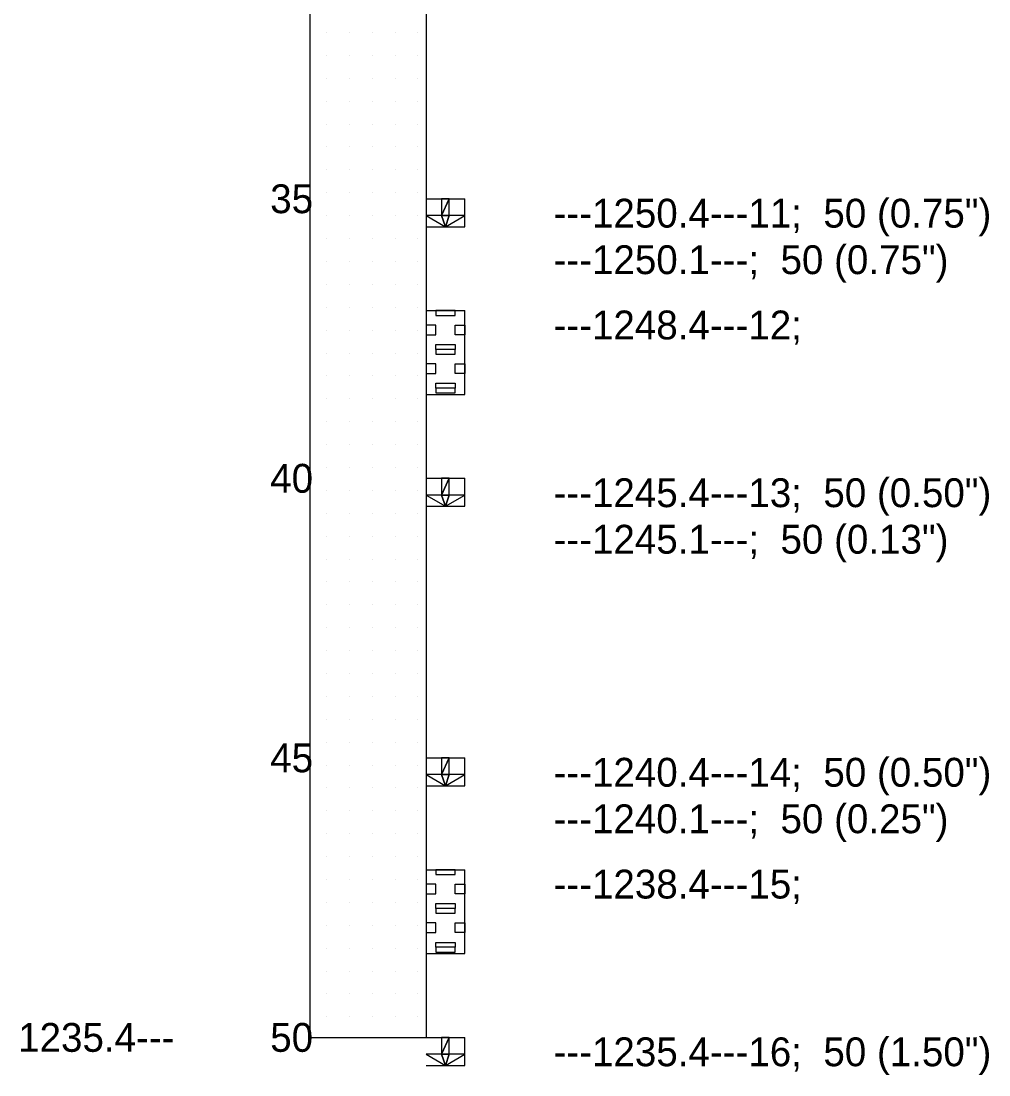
# Model space of a CAD drawing. Extents: x 2150148.6 to 2150220.1, y 143803.7 to 143875.1.
# Drawn here: x 2150175.114 to 2150179.278, y 143815.708 to 143820.239 of the extents above; entities that cross this region are included whole.
import ezdxf

# ---------------------------------------------------------------- set-up
doc = ezdxf.new("R2010")
doc.units = 0
doc.layers.add('Default', color=7, linetype='Continuous')

# ---------------------------------------------------------------- blocks, each defined once
blk = doc.blocks.new('POINT_DISPLAY')
at = {"layer": 'Default'}
blk.add_line((0, 0), (0, 0), dxfattribs=at)

msp = doc.modelspace()

# ---------------------------------------------------------------- linework, layer by layer
at = {"layer": 'Default'}
for points in [[(2150176.3564, 143827.8881), (2150176.3564, 143815.8689)], [(2150176.8564, 143827.8881), (2150176.8564, 143815.8689)], [(2150176.8564, 143819.4746), (2150177.023, 143819.4746)], [(2150177.023, 143819.3544), (2150177.023, 143819.4746)], [(2150176.8564, 143819.3544), (2150177.023, 143819.3544)], [(2150176.8564, 143818.9939), (2150177.023, 143818.9939)], [(2150177.023, 143818.6333), (2150177.023, 143818.9939)], [(2150176.8564, 143818.6333), (2150177.023, 143818.6333)], [(2150176.8564, 143818.2727), (2150177.023, 143818.2727)], [(2150177.023, 143818.1525), (2150177.023, 143818.2727)], [(2150176.8564, 143818.1525), (2150177.023, 143818.1525)], [(2150176.8564, 143817.0708), (2150177.023, 143817.0708)], [(2150177.023, 143816.9506), (2150177.023, 143817.0708)], [(2150176.8564, 143816.9506), (2150177.023, 143816.9506)], [(2150176.8564, 143816.59), (2150177.023, 143816.59)], [(2150177.023, 143816.2294), (2150177.023, 143816.59)], [(2150176.8564, 143816.2294), (2150177.023, 143816.2294)], [(2150176.3564, 143815.8689), (2150176.8564, 143815.8689)], [(2150176.8564, 143815.8689), (2150177.023, 143815.8689)], [(2150177.023, 143815.7487), (2150177.023, 143815.8689)], [(2150176.8564, 143815.7487), (2150177.023, 143815.7487)]]:
    msp.add_lwpolyline(points, dxfattribs=at)
for points in [[(2150176.923, 143819.4025), (2150176.9564, 143819.4025), (2150176.9564, 143819.4746), (2150176.923, 143819.4025)], [(2150176.923, 143819.4025), (2150176.9564, 143819.4746), (2150176.923, 143819.4746), (2150176.923, 143819.4025)], [(2150176.923, 143819.4025), (2150176.8564, 143819.4025), (2150176.9397, 143819.3544), (2150176.923, 143819.4025)], [(2150176.923, 143819.4025), (2150176.9397, 143819.3544), (2150176.9564, 143819.4025), (2150176.923, 143819.4025)], [(2150176.9397, 143819.3544), (2150177.023, 143819.4025), (2150176.9564, 143819.4025), (2150176.9397, 143819.3544)], [(2150176.898, 143818.9939), (2150176.898, 143818.973), (2150176.9814, 143818.973), (2150176.9814, 143818.9939)], [(2150176.8564, 143818.8897), (2150176.898, 143818.8897), (2150176.898, 143818.9314), (2150176.8564, 143818.9314)], [(2150177.023, 143818.8897), (2150176.9814, 143818.8897), (2150176.9814, 143818.9314), (2150177.023, 143818.9314)], [(2150176.898, 143818.8272), (2150176.898, 143818.848), (2150176.9814, 143818.848), (2150176.9814, 143818.8272)], [(2150176.898, 143818.8272), (2150176.898, 143818.8064), (2150176.9814, 143818.8064), (2150176.9814, 143818.8272)], [(2150176.8564, 143818.723), (2150176.898, 143818.723), (2150176.898, 143818.7647), (2150176.8564, 143818.7647)], [(2150177.023, 143818.723), (2150176.9814, 143818.723), (2150176.9814, 143818.7647), (2150177.023, 143818.7647)], [(2150176.898, 143818.6605), (2150176.898, 143818.6814), (2150176.9814, 143818.6814), (2150176.9814, 143818.6605)], [(2150176.898, 143818.6605), (2150176.898, 143818.6397), (2150176.9814, 143818.6397), (2150176.9814, 143818.6605)], [(2150176.923, 143818.2006), (2150176.9564, 143818.2006), (2150176.9564, 143818.2727), (2150176.923, 143818.2006)], [(2150176.923, 143818.2006), (2150176.9564, 143818.2727), (2150176.923, 143818.2727), (2150176.923, 143818.2006)], [(2150176.923, 143818.2006), (2150176.8564, 143818.2006), (2150176.9397, 143818.1525), (2150176.923, 143818.2006)], [(2150176.923, 143818.2006), (2150176.9397, 143818.1525), (2150176.9564, 143818.2006), (2150176.923, 143818.2006)], [(2150176.9397, 143818.1525), (2150177.023, 143818.2006), (2150176.9564, 143818.2006), (2150176.9397, 143818.1525)], [(2150176.923, 143816.9987), (2150176.9564, 143816.9987), (2150176.9564, 143817.0708), (2150176.923, 143816.9987)], [(2150176.923, 143816.9987), (2150176.9564, 143817.0708), (2150176.923, 143817.0708), (2150176.923, 143816.9987)], [(2150176.923, 143816.9987), (2150176.8564, 143816.9987), (2150176.9397, 143816.9506), (2150176.923, 143816.9987)], [(2150176.923, 143816.9987), (2150176.9397, 143816.9506), (2150176.9564, 143816.9987), (2150176.923, 143816.9987)], [(2150176.9397, 143816.9506), (2150177.023, 143816.9987), (2150176.9564, 143816.9987), (2150176.9397, 143816.9506)], [(2150176.898, 143816.59), (2150176.898, 143816.5692), (2150176.9814, 143816.5692), (2150176.9814, 143816.59)], [(2150176.8564, 143816.4858), (2150176.898, 143816.4858), (2150176.898, 143816.5275), (2150176.8564, 143816.5275)], [(2150177.023, 143816.4858), (2150176.9814, 143816.4858), (2150176.9814, 143816.5275), (2150177.023, 143816.5275)], [(2150176.898, 143816.4233), (2150176.898, 143816.4442), (2150176.9814, 143816.4442), (2150176.9814, 143816.4233)], [(2150176.898, 143816.4233), (2150176.898, 143816.4025), (2150176.9814, 143816.4025), (2150176.9814, 143816.4233)], [(2150176.8564, 143816.3192), (2150176.898, 143816.3192), (2150176.898, 143816.3609), (2150176.8564, 143816.3609)], [(2150177.023, 143816.3192), (2150176.9814, 143816.3192), (2150176.9814, 143816.3609), (2150177.023, 143816.3609)], [(2150176.898, 143816.2567), (2150176.898, 143816.2775), (2150176.9814, 143816.2775), (2150176.9814, 143816.2567)], [(2150176.898, 143816.2567), (2150176.898, 143816.2359), (2150176.9814, 143816.2359), (2150176.9814, 143816.2567)], [(2150176.923, 143815.7967), (2150176.9564, 143815.7967), (2150176.9564, 143815.8689), (2150176.923, 143815.7967)], [(2150176.923, 143815.7967), (2150176.9564, 143815.8689), (2150176.923, 143815.8689), (2150176.923, 143815.7967)], [(2150176.923, 143815.7967), (2150176.8564, 143815.7967), (2150176.9397, 143815.7487), (2150176.923, 143815.7967)], [(2150176.923, 143815.7967), (2150176.9397, 143815.7487), (2150176.9564, 143815.7967), (2150176.923, 143815.7967)], [(2150176.9397, 143815.7487), (2150177.023, 143815.7967), (2150176.9564, 143815.7967), (2150176.9397, 143815.7487)]]:
    msp.add_lwpolyline(points, close=True, dxfattribs=at)

# ---------------------------------------------------------------- block references
at = {"layer": 'Default', "xscale": 0.39369999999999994, "yscale": 0.3936999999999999}
for p in [(2150176.4275, 143820.1893), (2150176.5259, 143820.1893), (2150176.6244, 143820.1893), (2150176.7228, 143820.1893), (2150176.8212, 143820.1893), (2150176.4275, 143820.0909), (2150176.5259, 143820.0909), (2150176.6244, 143820.0909), (2150176.7228, 143820.0909), (2150176.8212, 143820.0909), (2150176.4275, 143819.9925), (2150176.5259, 143819.9925), (2150176.6244, 143819.9925), (2150176.7228, 143819.9925), (2150176.8212, 143819.9925), (2150176.4275, 143819.8941), (2150176.5259, 143819.8941), (2150176.6244, 143819.8941), (2150176.7228, 143819.8941), (2150176.8212, 143819.8941), (2150176.4275, 143819.7956), (2150176.5259, 143819.7956), (2150176.6244, 143819.7956), (2150176.7228, 143819.7956), (2150176.8212, 143819.7956), (2150176.4275, 143819.6972), (2150176.5259, 143819.6972), (2150176.6244, 143819.6972), (2150176.7228, 143819.6972), (2150176.8212, 143819.6972), (2150176.4275, 143819.5988), (2150176.5259, 143819.5988), (2150176.6244, 143819.5988), (2150176.7228, 143819.5988), (2150176.8212, 143819.5988), (2150176.4275, 143819.5004), (2150176.5259, 143819.5004), (2150176.6244, 143819.5004), (2150176.7228, 143819.5004), (2150176.8212, 143819.5004), (2150176.4275, 143819.4019), (2150176.5259, 143819.4019), (2150176.6244, 143819.4019), (2150176.7228, 143819.4019), (2150176.8212, 143819.4019), (2150176.4275, 143819.3035), (2150176.5259, 143819.3035), (2150176.6244, 143819.3035), (2150176.7228, 143819.3035), (2150176.8212, 143819.3035), (2150176.4275, 143819.2051), (2150176.5259, 143819.2051), (2150176.6244, 143819.2051), (2150176.7228, 143819.2051), (2150176.8212, 143819.2051), (2150176.4275, 143819.1067), (2150176.5259, 143819.1067), (2150176.6244, 143819.1067), (2150176.7228, 143819.1067), (2150176.8212, 143819.1067), (2150176.4275, 143819.0082), (2150176.5259, 143819.0082), (2150176.6244, 143819.0082), (2150176.7228, 143819.0082), (2150176.8212, 143819.0082), (2150176.4275, 143818.9098), (2150176.5259, 143818.9098), (2150176.6244, 143818.9098), (2150176.7228, 143818.9098), (2150176.8212, 143818.9098), (2150176.4275, 143818.8114), (2150176.5259, 143818.8114), (2150176.6244, 143818.8114), (2150176.7228, 143818.8114), (2150176.8212, 143818.8114), (2150176.4275, 143818.713), (2150176.5259, 143818.713), (2150176.6244, 143818.713), (2150176.7228, 143818.713), (2150176.8212, 143818.713), (2150176.4275, 143818.6145), (2150176.5259, 143818.6145), (2150176.6244, 143818.6145), (2150176.7228, 143818.6145), (2150176.8212, 143818.6145), (2150176.4275, 143818.5161), (2150176.5259, 143818.5161), (2150176.6244, 143818.5161), (2150176.7228, 143818.5161), (2150176.8212, 143818.5161), (2150176.4275, 143818.4177), (2150176.5259, 143818.4177), (2150176.6244, 143818.4177), (2150176.7228, 143818.4177), (2150176.8212, 143818.4177), (2150176.4275, 143818.3193), (2150176.5259, 143818.3193), (2150176.6244, 143818.3193), (2150176.7228, 143818.3193), (2150176.8212, 143818.3193), (2150176.4275, 143818.2208), (2150176.5259, 143818.2208), (2150176.6244, 143818.2208), (2150176.7228, 143818.2208), (2150176.8212, 143818.2208), (2150176.4275, 143818.1224), (2150176.5259, 143818.1224), (2150176.6244, 143818.1224), (2150176.7228, 143818.1224), (2150176.8212, 143818.1224), (2150176.4275, 143818.024), (2150176.5259, 143818.024), (2150176.6244, 143818.024), (2150176.7228, 143818.024), (2150176.8212, 143818.024), (2150176.4275, 143817.9256), (2150176.5259, 143817.9256), (2150176.6244, 143817.9256), (2150176.7228, 143817.9256), (2150176.8212, 143817.9256), (2150176.4275, 143817.8271), (2150176.5259, 143817.8271), (2150176.6244, 143817.8271), (2150176.7228, 143817.8271), (2150176.8212, 143817.8271), (2150176.4275, 143817.7287), (2150176.5259, 143817.7287), (2150176.6244, 143817.7287), (2150176.7228, 143817.7287), (2150176.8212, 143817.7287), (2150176.4275, 143817.6303), (2150176.5259, 143817.6303), (2150176.6244, 143817.6303), (2150176.7228, 143817.6303), (2150176.8212, 143817.6303), (2150176.4275, 143817.5319), (2150176.5259, 143817.5319), (2150176.6244, 143817.5319), (2150176.7228, 143817.5319), (2150176.8212, 143817.5319), (2150176.4275, 143817.4334), (2150176.5259, 143817.4334), (2150176.6244, 143817.4334), (2150176.7228, 143817.4334), (2150176.8212, 143817.4334), (2150176.4275, 143817.335), (2150176.5259, 143817.335), (2150176.6244, 143817.335), (2150176.7228, 143817.335), (2150176.8212, 143817.335), (2150176.4275, 143817.2366), (2150176.5259, 143817.2366), (2150176.6244, 143817.2366), (2150176.7228, 143817.2366), (2150176.8212, 143817.2366), (2150176.4275, 143817.1382), (2150176.5259, 143817.1382), (2150176.6244, 143817.1382), (2150176.7228, 143817.1382), (2150176.8212, 143817.1382), (2150176.4275, 143817.0397), (2150176.5259, 143817.0397), (2150176.6244, 143817.0397), (2150176.7228, 143817.0397), (2150176.8212, 143817.0397), (2150176.4275, 143816.9413), (2150176.5259, 143816.9413), (2150176.6244, 143816.9413), (2150176.7228, 143816.9413), (2150176.8212, 143816.9413), (2150176.4275, 143816.8429), (2150176.5259, 143816.8429), (2150176.6244, 143816.8429), (2150176.7228, 143816.8429), (2150176.8212, 143816.8429), (2150176.4275, 143816.7445), (2150176.5259, 143816.7445), (2150176.6244, 143816.7445), (2150176.7228, 143816.7445), (2150176.8212, 143816.7445), (2150176.4275, 143816.646), (2150176.5259, 143816.646), (2150176.6244, 143816.646), (2150176.7228, 143816.646), (2150176.8212, 143816.646), (2150176.4275, 143816.5476), (2150176.5259, 143816.5476), (2150176.6244, 143816.5476), (2150176.7228, 143816.5476), (2150176.8212, 143816.5476), (2150176.4275, 143816.4492), (2150176.5259, 143816.4492), (2150176.6244, 143816.4492), (2150176.7228, 143816.4492), (2150176.8212, 143816.4492), (2150176.4275, 143816.3508), (2150176.5259, 143816.3508), (2150176.6244, 143816.3508), (2150176.7228, 143816.3508), (2150176.8212, 143816.3508), (2150176.4275, 143816.2523), (2150176.5259, 143816.2523), (2150176.6244, 143816.2523), (2150176.7228, 143816.2523), (2150176.8212, 143816.2523), (2150176.4275, 143816.1539), (2150176.5259, 143816.1539), (2150176.6244, 143816.1539), (2150176.7228, 143816.1539), (2150176.8212, 143816.1539), (2150176.4275, 143816.0555), (2150176.5259, 143816.0555), (2150176.6244, 143816.0555), (2150176.7228, 143816.0555), (2150176.8212, 143816.0555), (2150176.4275, 143815.9571), (2150176.5259, 143815.9571), (2150176.6244, 143815.9571), (2150176.7228, 143815.9571), (2150176.8212, 143815.9571)]:
    msp.add_blockref('POINT_DISPLAY', p, dxfattribs=at)

# ---------------------------------------------------------------- texts
at = {"layer": 'Default'}
for s, p in [('35', (2150176.1859, 143819.4126)), ('---1250.4---11;  50 (0.75")', (2150177.4044, 143819.3506)), ('---1250.1---;  50 (0.75")', (2150177.4044, 143819.1506)), ('---1248.4---12;', (2150177.4044, 143818.8699)), ('40', (2150176.1859, 143818.2107)), ('---1245.4---13;  50 (0.50")', (2150177.4044, 143818.1487)), ('---1245.1---;  50 (0.13")', (2150177.4044, 143817.9487)), ('45', (2150176.1859, 143817.0088)), ('---1240.4---14;  50 (0.50")', (2150177.4044, 143816.9468)), ('---1240.1---;  50 (0.25")', (2150177.4044, 143816.7468)), ('---1238.4---15;', (2150177.4044, 143816.466)), ('1235.4---', (2150175.1015, 143815.8069)), ('50', (2150176.1859, 143815.8069)), ('---1235.4---16;  50 (1.50")', (2150177.4044, 143815.7449))]:
    msp.add_text(s, height=0.124, dxfattribs=at).set_placement(p)

doc.saveas('drawing.dxf')
